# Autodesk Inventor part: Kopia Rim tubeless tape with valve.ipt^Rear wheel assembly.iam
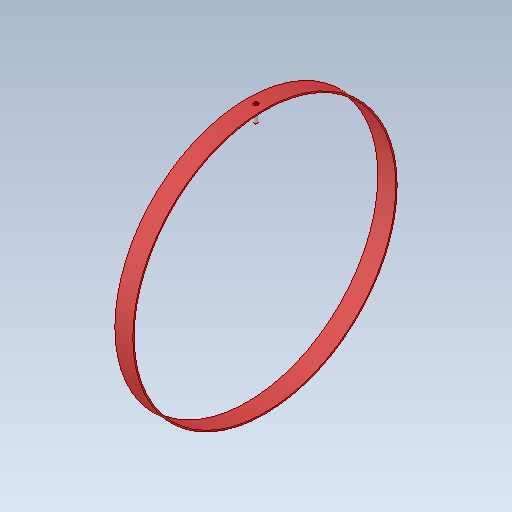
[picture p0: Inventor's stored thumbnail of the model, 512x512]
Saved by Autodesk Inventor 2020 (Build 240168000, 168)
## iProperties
Created: 2017-09
Part Number: Kopia Rim tubeless tape with valve.ipt^Rear wheel assembly.iam
Material: Ogólny
Document SubType Name: Modeling
Designer: Tomasz
Density: 1 g/cm^3
Appearance: Domyślna
Sending System: SolidWorks 2017
Last Author: Tomasz
Last Saved: 2017-09-11
Author: Tomasz
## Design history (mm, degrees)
feature "Rim tubeless tape with valve.ipt"
node "Bryła1"
